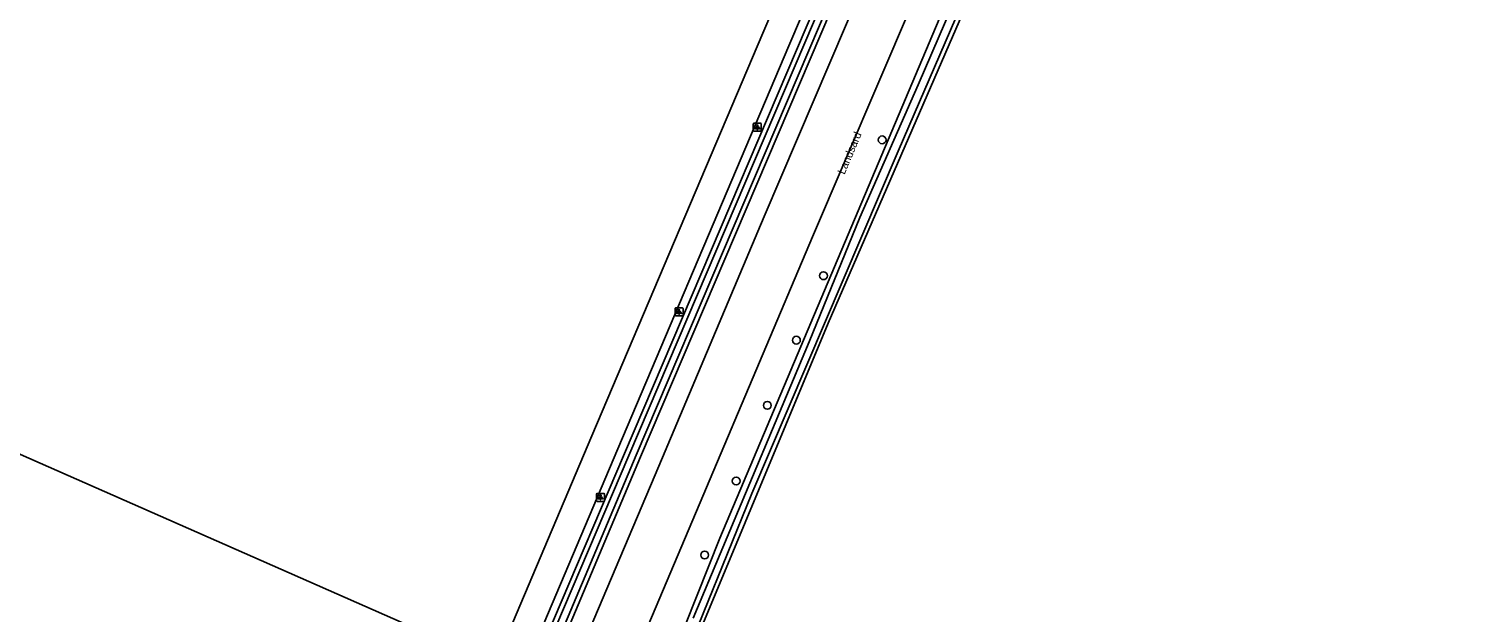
# Model space of a CAD drawing. Extents: x 155209 to 156823, y 385356 to 388482.
# Drawn here: x 155996.3 to 156177.7, y 386329.7 to 386402.7 of the extents above; entities that cross this region are included whole.
import ezdxf

# ---------------------------------------------------------------- set-up
doc = ezdxf.new("R2010")
doc.units = 0
for name, color, linetype in [('IMGEO_Boom', 7, 'Continuous'), ('IMGEO_Fietspad_gesloten', 7, 'Continuous'), ('IMGEO_Gemengd_bos', 7, 'Continuous'), ('IMGEO_Groenvoorziening', 7, 'Continuous'), ('IMGEO_Lichtpunt', 7, 'Continuous'), ('IMGEO_Openbare_ruimte_label', 7, 'Continuous'), ('IMGEO_Rijbaan_lokaal_gesloten', 7, 'Continuous'), ('IMGEO_Waterloop', 7, 'Continuous')]:
    doc.layers.add(name, color=color, linetype=linetype)

msp = doc.modelspace()

# ---------------------------------------------------------------- linework, layer by layer
at = {"layer": 'IMGEO_Boom'}
for centre in [(156102.88, 386388.85), (156095.55, 386371.87), (156092.17, 386363.81), (156088.53, 386355.67), (156084.64, 386346.21), (156080.7, 386336.96)]:
    msp.add_circle(centre, 0.489, dxfattribs=at)
at = {"layer": 'IMGEO_Fietspad_gesloten'}
for points in [[(156142.59, 386521.01), (156114.61, 386455.4), (156091.23, 386400.62), (156069.84, 386350.23), (156058.06, 386322.41), (156046.41, 386294.89), (156023.01, 386239.56), (156010, 386208.82), (156005, 386197.04)], [(156125.52, 386490.13), (156111.26, 386456.76), (156087.98, 386402.17), (156066.59, 386351.85), (156054.72, 386323.81), (156054.54, 386323.39)]]:
    msp.add_lwpolyline(points, dxfattribs=at)
at = {"layer": 'IMGEO_Gemengd_bos'}
for points in [[(156070.14, 386302.11), (156080.46, 386328.34), (156096.12, 386365.96), (156141.39, 386470.18), (156150.93, 386490.49), (156158.36, 386508.88), (156163.81, 386521.3), (156167.26, 386529.54), (156172.79, 386541.9), (156173.42, 386543.01), (156176.13, 386545.72), (156177.73, 386546.35)], [(155881.05, 386399.78), (156052.24, 386324.4)]]:
    msp.add_lwpolyline(points, dxfattribs=at)
at = {"layer": 'IMGEO_Groenvoorziening'}
for points in [[(156063.56, 386292.58), (156064.47, 386293.87), (156065.2, 386295.28), (156082.6, 386339.09), (156140.39, 386475.84), (156151.1, 386500.48), (156159.62, 386521.29), (156166.27, 386536.26), (156169.74, 386543.04), (156171.1, 386545.31), (156172.2, 386546.57), (156173.2, 386547.64)], [(156144.95, 386523.89), (156070.68, 386349.65), (156026.29, 386245.49)], [(156028.61, 386244.59), (156072.67, 386349.22), (156146.86, 386523.08)]]:
    msp.add_lwpolyline(points, dxfattribs=at)
at = {"layer": 'IMGEO_Lichtpunt'}
for p, q in [((156086.78, 386390.84), (156086.78, 386390.03)), ((156086.78, 386390.84), (156086.78, 386390.03)), ((156087.69, 386390.94), (156086.88, 386390.94)), ((156087.69, 386390.94), (156086.88, 386390.94)), ((156086.88, 386389.94), (156087.69, 386389.94)), ((156086.88, 386389.94), (156087.69, 386389.94)), ((156087.78, 386390.03), (156087.78, 386390.84)), ((156087.78, 386390.03), (156087.78, 386390.84)), ((156077, 386367.75), (156077, 386366.95)), ((156077, 386367.75), (156077, 386366.95)), ((156077.9, 386367.85), (156077.1, 386367.85)), ((156077.9, 386367.85), (156077.1, 386367.85)), ((156078, 386366.95), (156078, 386367.75)), ((156078, 386366.95), (156078, 386367.75)), ((156077.1, 386366.85), (156077.9, 386366.85)), ((156077.1, 386366.85), (156077.9, 386366.85)), ((156067.18, 386344.57), (156067.18, 386343.77)), ((156067.18, 386344.57), (156067.18, 386343.77)), ((156068.08, 386344.67), (156067.27, 386344.67)), ((156068.08, 386344.67), (156067.27, 386344.67)), ((156068.17, 386343.77), (156068.17, 386344.57)), ((156068.17, 386343.77), (156068.17, 386344.57)), ((156067.27, 386343.67), (156068.08, 386343.67)), ((156067.27, 386343.67), (156068.08, 386343.67))]:
    msp.add_line(p, q, dxfattribs=at)
for points in [[(156087.16, 386390.5), (156087.2, 386390.48), (156087.01, 386390.21), (156086.97, 386390.24), (156087.16, 386390.5)], [(156087.26, 386390.46), (156087.31, 386390.46), (156087.31, 386390.13), (156087.26, 386390.13), (156087.26, 386390.46)], [(156087.37, 386390.48), (156087.41, 386390.5), (156087.59, 386390.24), (156087.56, 386390.21), (156087.37, 386390.48)], [(156077.38, 386367.42), (156077.41, 386367.39), (156077.23, 386367.13), (156077.19, 386367.15), (156077.38, 386367.42)], [(156077.48, 386367.37), (156077.53, 386367.37), (156077.53, 386367.05), (156077.48, 386367.05), (156077.48, 386367.37)], [(156077.59, 386367.39), (156077.63, 386367.42), (156077.81, 386367.15), (156077.77, 386367.13), (156077.59, 386367.39)], [(156067.55, 386344.24), (156067.59, 386344.21), (156067.4, 386343.95), (156067.36, 386343.97), (156067.55, 386344.24)], [(156067.65, 386344.19), (156067.7, 386344.19), (156067.7, 386343.87), (156067.65, 386343.87), (156067.65, 386344.19)], [(156067.76, 386344.21), (156067.8, 386344.24), (156067.99, 386343.97), (156067.95, 386343.95), (156067.76, 386344.21)]]:
    msp.add_lwpolyline(points, dxfattribs=at)
for centre in [(156087.28, 386390.64), (156077.5, 386367.55), (156067.68, 386344.37)]:
    msp.add_circle(centre, 0.0994, dxfattribs=at)
for centre, start, end in [((156086.88, 386390.84), 90, 180), ((156086.88, 386390.84), 90, 180), ((156086.88, 386390.03), 180, 270), ((156086.88, 386390.03), 180, 270), ((156087.69, 386390.84), 0, 90), ((156087.69, 386390.84), 0, 90), ((156087.69, 386390.03), 270, 0), ((156087.69, 386390.03), 270, 360), ((156077.1, 386367.75), 90, 180), ((156077.1, 386367.75), 90, 180), ((156077.9, 386367.75), 0, 90), ((156077.9, 386367.75), 0, 90), ((156077.1, 386366.95), 180, 270), ((156077.1, 386366.95), 180, 270), ((156077.9, 386366.95), 270, 0), ((156077.9, 386366.95), 270, 360), ((156067.27, 386344.57), 90, 180), ((156067.27, 386344.57), 90, 180), ((156068.08, 386344.57), 0, 90), ((156068.08, 386344.57), 0, 90), ((156067.27, 386343.77), 180, 270), ((156067.27, 386343.77), 180, 270), ((156068.08, 386343.77), 270, 0), ((156068.08, 386343.77), 270, 360)]:
    msp.add_arc(centre, 0.0946, start, end, dxfattribs=at)
at = {"layer": 'IMGEO_Rijbaan_lokaal_gesloten'}
for points in [[(156010.67, 386196.17), (156028.11, 386237.4), (156051.19, 386291.96), (156074.96, 386348.06), (156088.15, 386379.28), (156100.53, 386408.28), (156128.81, 386474.42), (156158.86, 386544.7), (156160.63, 386548.86)], [(156164.88, 386542.11), (156134.86, 386471.86), (156106.55, 386405.65), (156094.2, 386376.75), (156080.93, 386345.4), (156057.35, 386289.66), (156034.16, 386234.85), (156023.57, 386209.85)]]:
    msp.add_lwpolyline(points, dxfattribs=at)
at = {"layer": 'IMGEO_Waterloop'}
for points in [[(156145.41, 386523.44), (156071.23, 386349.41), (156026.79, 386245.14)], [(156027.95, 386244.58), (156072.12, 386349.46), (156146.22, 386523.1)], [(156079.27, 386329.07), (156093.76, 386363.6), (156100.11, 386379.14), (156107.37, 386395.72), (156123.57, 386433.22)], [(156117.96, 386417.73), (156104.89, 386387.44), (156086.6, 386344.66), (156074.44, 386314.65)]]:
    msp.add_lwpolyline(points, dxfattribs=at)

# ---------------------------------------------------------------- texts
at = {"layer": 'IMGEO_Openbare_ruimte_label'}
msp.add_text('Landsard', height=1, rotation=67.1552, dxfattribs=at).set_placement((156098.18, 386384.45))

doc.saveas('drawing.dxf')
